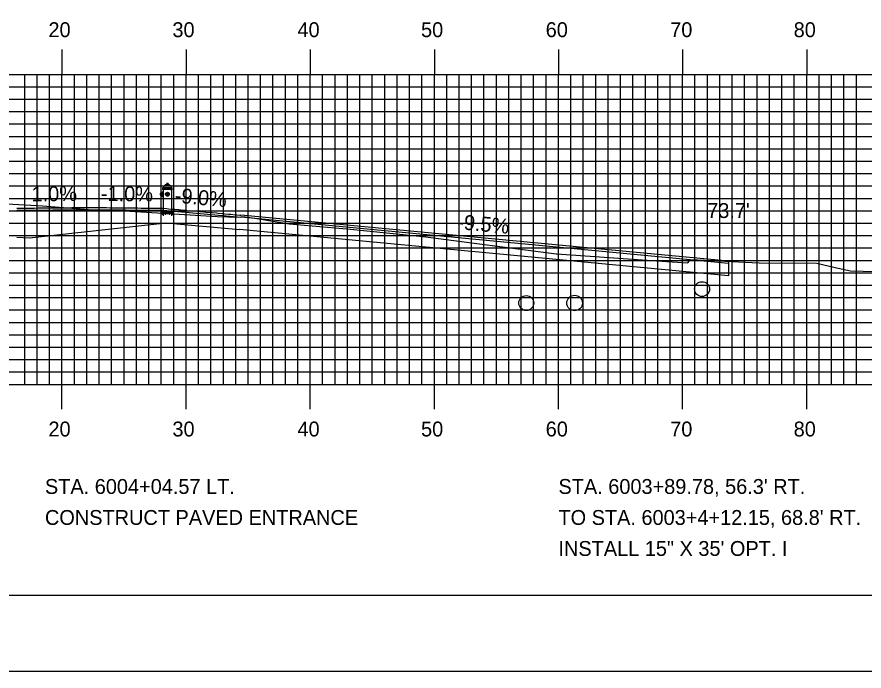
# Model space of a CAD drawing. Extents: x 852087 to 852430, y 366898 to 367118.
# Drawn here: x 852268.9 to 852337.2, y 366898.4 to 366951.1 of the extents above; entities that cross this region are included whole.
import ezdxf

# ---------------------------------------------------------------- set-up
doc = ezdxf.new("R2010")
doc.units = 0
for name, color, linetype in [('ANNOTATION', 7, 'Continuous'), ('BORDER', 7, 'Continuous'), ('D_Roadway_Centerline', 7, 'Continuous'), ('D_Roadway_Drive_Paved_RT', 7, 'Continuous'), ('D_Roadway_Drive_SubGrade', 7, 'Continuous'), ('D_Text_Standard', 7, 'Continuous'), ('H_V ANNOTATION', 7, 'Continuous'), ('MAJOR', 7, 'Continuous'), ('MINOR', 7, 'Continuous'), ('PLOT BOUNDARY', 7, 'Continuous'), ('S_Drainage_Invert', 7, 'Continuous'), ('S_Roadway_Centerline', 7, 'Continuous'), ('S_Utilities_Hydrant', 7, 'Continuous')]:
    doc.layers.add(name, color=color, linetype=linetype)

msp = doc.modelspace()

# ---------------------------------------------------------------- linework, layer by layer
at = {"layer": 'BORDER'}
msp.add_lwpolyline([(852102.931, 366904.473), (852422.931, 366904.473), (852422.931, 367114.473), (852102.931, 367114.473)], close=True, dxfattribs=at)
at = {"layer": 'D_Roadway_Centerline'}
msp.add_line((852326.234, 366931.398), (852286.944, 366935.114), dxfattribs=at)
msp.add_lwpolyline([(852268.9, 366935.68), (852269.116, 366935.682), (852269.261, 366935.684), (852269.616, 366935.687), (852269.771, 366935.689), (852270.117, 366935.692), (852270.28, 366935.694), (852270.617, 366935.697), (852270.79, 366935.699), (852271.117, 366935.702), (852271.299, 366935.704), (852271.617, 366935.707), (852271.808, 366935.709), (852272.118, 366935.712), (852272.317, 366935.714), (852272.618, 366935.717), (852272.826, 366935.719), (852273.118, 366935.722), (852273.334, 366935.724), (852273.618, 366935.727), (852273.843, 366935.73), (852274.119, 366935.732), (852274.352, 366935.735), (852274.619, 366935.737), (852274.645, 366935.738), (852274.675, 366935.738), (852274.889, 366935.736), (852275.119, 366935.733), (852275.368, 366935.731), (852275.619, 366935.728), (852275.876, 366935.726), (852276.119, 366935.723), (852276.384, 366935.721), (852276.62, 366935.718), (852276.892, 366935.716), (852277.12, 366935.713), (852277.4, 366935.711), (852277.62, 366935.708), (852277.907, 366935.706), (852278.12, 366935.703), (852278.413, 366935.7), (852278.621, 366935.698), (852278.92, 366935.695), (852279.121, 366935.693), (852279.426, 366935.69), (852279.621, 366935.688), (852279.931, 366935.685), (852280.121, 366935.683), (852280.436, 366935.68), (852280.622, 366935.678), (852280.657, 366935.678), (852280.677, 366935.678), (852280.961, 366935.652), (852281.122, 366935.638), (852281.444, 366935.609), (852281.622, 366935.593), (852281.948, 366935.564), (852282.122, 366935.548), (852282.451, 366935.518), (852282.622, 366935.503), (852282.955, 366935.473), (852283.123, 366935.458), (852283.458, 366935.428), (852283.623, 366935.413), (852283.962, 366935.382), (852284.123, 366935.368), (852284.466, 366935.337), (852284.623, 366935.323), (852284.969, 366935.292), (852285.124, 366935.278), (852285.473, 366935.246), (852285.624, 366935.233), (852285.977, 366935.201), (852286.124, 366935.188), (852286.481, 366935.156), (852286.624, 366935.143), (852286.854, 366935.122), (852286.944, 366935.114)], dxfattribs=at)
msp.add_circle((852313.831, 366928.029), 0.625, dxfattribs=at)
at = {"layer": 'D_Roadway_Drive_Paved_RT'}
msp.add_line((852326.234, 366931.231), (852286.929, 366934.948), dxfattribs=at)
msp.add_lwpolyline([(852268.902, 366935.513), (852274.675, 366935.571), (852280.669, 366935.511), (852286.929, 366934.948)], dxfattribs=at)
at = {"layer": 'D_Roadway_Drive_SubGrade'}
for p, q in [((852269.9, 366933.299), (852280.9, 366934.486)), ((852326.234, 366930.226), (852286.834, 366933.953)), ((852268.9, 366933.347), (852269.9, 366933.299)), ((852326.234, 366931.398), (852326.234, 366930.226))]:
    msp.add_line(p, q, dxfattribs=at)
msp.add_lwpolyline([(852280.9, 366934.486), (852286.84, 366933.952)], dxfattribs=at)
at = {"layer": 'MAJOR'}
for p, q in [((852272.531, 366948.477), (852272.531, 366946.473)), ((852282.531, 366948.477), (852282.531, 366946.473)), ((852292.531, 366948.477), (852292.531, 366946.473)), ((852302.531, 366948.477), (852302.531, 366946.473)), ((852312.531, 366948.477), (852312.531, 366946.473)), ((852322.531, 366948.477), (852322.531, 366946.473)), ((852332.531, 366948.477), (852332.531, 366946.473)), ((852112.531, 366946.473), (852392.531, 366946.473)), ((852112.531, 366946.473), (852392.531, 366946.473)), ((852272.531, 366921.473), (852272.531, 366946.473)), ((852282.531, 366921.473), (852282.531, 366946.473)), ((852292.531, 366921.473), (852292.531, 366946.473)), ((852302.531, 366921.473), (852302.531, 366946.473)), ((852312.531, 366921.473), (852312.531, 366946.473)), ((852322.531, 366921.473), (852322.531, 366946.473)), ((852332.531, 366921.473), (852332.531, 366946.473)), ((852112.531, 366941.473), (852392.531, 366941.473)), ((852112.531, 366936.473), (852392.531, 366936.473)), ((852112.531, 366931.473), (852392.531, 366931.473)), ((852112.531, 366926.473), (852392.531, 366926.473)), ((852112.531, 366921.473), (852392.531, 366921.473)), ((852112.531, 366921.473), (852392.531, 366921.473)), ((852272.531, 366919.469), (852272.531, 366921.473)), ((852282.531, 366919.469), (852282.531, 366921.473)), ((852292.531, 366919.469), (852292.531, 366921.473)), ((852302.531, 366919.469), (852302.531, 366921.473)), ((852312.531, 366919.469), (852312.531, 366921.473)), ((852322.531, 366919.469), (852322.531, 366921.473)), ((852332.531, 366919.469), (852332.531, 366921.473))]:
    msp.add_line(p, q, dxfattribs=at)
at = {"layer": 'MINOR'}
for p, q in [((852269.531, 366921.473), (852269.531, 366946.473)), ((852270.531, 366921.473), (852270.531, 366946.473)), ((852271.531, 366921.473), (852271.531, 366946.473)), ((852273.531, 366921.473), (852273.531, 366946.473)), ((852274.531, 366921.473), (852274.531, 366946.473)), ((852275.531, 366921.473), (852275.531, 366946.473)), ((852276.531, 366921.473), (852276.531, 366946.473)), ((852277.531, 366921.473), (852277.531, 366946.473)), ((852278.531, 366921.473), (852278.531, 366946.473)), ((852279.531, 366921.473), (852279.531, 366946.473)), ((852280.531, 366921.473), (852280.531, 366946.473)), ((852281.531, 366921.473), (852281.531, 366946.473)), ((852283.531, 366921.473), (852283.531, 366946.473)), ((852284.531, 366921.473), (852284.531, 366946.473)), ((852285.531, 366921.473), (852285.531, 366946.473)), ((852286.531, 366921.473), (852286.531, 366946.473)), ((852287.531, 366921.473), (852287.531, 366946.473)), ((852288.531, 366921.473), (852288.531, 366946.473)), ((852289.531, 366921.473), (852289.531, 366946.473)), ((852290.531, 366921.473), (852290.531, 366946.473)), ((852291.531, 366921.473), (852291.531, 366946.473)), ((852293.531, 366921.473), (852293.531, 366946.473)), ((852294.531, 366921.473), (852294.531, 366946.473)), ((852295.531, 366921.473), (852295.531, 366946.473)), ((852296.531, 366921.473), (852296.531, 366946.473)), ((852297.531, 366921.473), (852297.531, 366946.473)), ((852298.531, 366921.473), (852298.531, 366946.473)), ((852299.531, 366921.473), (852299.531, 366946.473)), ((852300.531, 366921.473), (852300.531, 366946.473)), ((852301.531, 366921.473), (852301.531, 366946.473)), ((852303.531, 366921.473), (852303.531, 366946.473)), ((852304.531, 366921.473), (852304.531, 366946.473)), ((852305.531, 366921.473), (852305.531, 366946.473)), ((852306.531, 366921.473), (852306.531, 366946.473)), ((852307.531, 366921.473), (852307.531, 366946.473)), ((852308.531, 366921.473), (852308.531, 366946.473)), ((852309.531, 366921.473), (852309.531, 366946.473)), ((852310.531, 366921.473), (852310.531, 366946.473)), ((852311.531, 366921.473), (852311.531, 366946.473)), ((852313.531, 366921.473), (852313.531, 366946.473)), ((852314.531, 366921.473), (852314.531, 366946.473)), ((852315.531, 366921.473), (852315.531, 366946.473)), ((852316.531, 366921.473), (852316.531, 366946.473)), ((852317.531, 366921.473), (852317.531, 366946.473)), ((852318.531, 366921.473), (852318.531, 366946.473)), ((852319.531, 366921.473), (852319.531, 366946.473)), ((852320.531, 366921.473), (852320.531, 366946.473)), ((852321.531, 366921.473), (852321.531, 366946.473)), ((852323.531, 366921.473), (852323.531, 366946.473)), ((852324.531, 366921.473), (852324.531, 366946.473)), ((852325.531, 366921.473), (852325.531, 366946.473)), ((852326.531, 366921.473), (852326.531, 366946.473)), ((852327.531, 366921.473), (852327.531, 366946.473)), ((852328.531, 366921.473), (852328.531, 366946.473)), ((852329.531, 366921.473), (852329.531, 366946.473)), ((852330.531, 366921.473), (852330.531, 366946.473)), ((852331.531, 366921.473), (852331.531, 366946.473)), ((852333.531, 366921.473), (852333.531, 366946.473)), ((852334.531, 366921.473), (852334.531, 366946.473)), ((852335.531, 366921.473), (852335.531, 366946.473)), ((852336.531, 366921.473), (852336.531, 366946.473)), ((852112.531, 366945.473), (852392.531, 366945.473)), ((852112.531, 366944.473), (852392.531, 366944.473)), ((852112.531, 366943.473), (852392.531, 366943.473)), ((852112.531, 366942.473), (852392.531, 366942.473)), ((852112.531, 366940.473), (852392.531, 366940.473)), ((852112.531, 366939.473), (852392.531, 366939.473)), ((852112.531, 366938.473), (852392.531, 366938.473)), ((852112.531, 366937.473), (852392.531, 366937.473)), ((852112.531, 366935.473), (852392.531, 366935.473)), ((852112.531, 366934.473), (852392.531, 366934.473)), ((852112.531, 366933.473), (852392.531, 366933.473)), ((852112.531, 366932.473), (852392.531, 366932.473)), ((852112.531, 366930.473), (852392.531, 366930.473)), ((852112.531, 366929.473), (852392.531, 366929.473)), ((852112.531, 366928.473), (852392.531, 366928.473)), ((852112.531, 366927.473), (852392.531, 366927.473)), ((852112.531, 366925.473), (852392.531, 366925.473)), ((852112.531, 366924.473), (852392.531, 366924.473)), ((852112.531, 366923.473), (852392.531, 366923.473)), ((852112.531, 366922.473), (852392.531, 366922.473))]:
    msp.add_line(p, q, dxfattribs=at)
at = {"layer": 'PLOT BOUNDARY'}
msp.add_lwpolyline([(852086.744, 366898.355), (852426.744, 366898.355), (852426.744, 367118.355), (852086.744, 367118.355)], close=True, dxfattribs=at)
at = {"layer": 'S_Drainage_Invert'}
for centre in [(852324.1, 366929.153), (852309.934, 366928.029)]:
    msp.add_circle(centre, 0.6, dxfattribs=at)
at = {"layer": 'S_Roadway_Centerline'}
msp.add_lwpolyline([(852265.692, 366936.178), (852270.959, 366935.859), (852275.688, 366935.504), (852277.536, 366935.463), (852280.218, 366935.302), (852285.045, 366935.019), (852286.748, 366934.969), (852287.106, 366935.015), (852288.227, 366934.848), (852290.827, 366934.417), (852295.786, 366933.99), (852296.825, 366933.883), (852301.329, 366933.423), (852301.551, 366933.405), (852301.618, 366933.399), (852312.348, 366932.011), (852312.406, 366931.999), (852320.438, 366931.424), (852322.942, 366931.276), (852323.159, 366931.547), (852328.693, 366931.279), (852333.354, 366931.242), (852334.838, 366930.897), (852336.074, 366930.619), (852341.222, 366930.486)], dxfattribs=at)
at = {"layer": 'S_Utilities_Hydrant'}
for p, q in [((852281.404, 366937.313), (852280.648, 366937.313)), ((852280.726, 366937.441), (852280.688, 366937.313)), ((852280.707, 366937.313), (852280.707, 366937.331)), ((852280.735, 366937.331), (852280.735, 366937.313)), ((852281.026, 366937.512), (852280.795, 366937.512)), ((852280.873, 366937.569), (852281.178, 366937.569)), ((852280.913, 366937.609), (852280.913, 366937.569)), ((852281.121, 366937.625), (852280.929, 366937.624)), ((852281.026, 366937.512), (852281.257, 366937.512)), ((852281.138, 366937.569), (852281.138, 366937.609)), ((852281.316, 366937.331), (852281.316, 366937.313)), ((852281.325, 366937.441), (852281.364, 366937.313)), ((852281.345, 366937.313), (852281.345, 366937.331)), ((852280.484, 366936.854), (852280.484, 366936.852)), ((852280.484, 366936.852), (852280.484, 366936.762)), ((852280.484, 366936.759), (852280.484, 366936.762)), ((852280.495, 366936.867), (852280.495, 366936.746)), ((852280.499, 366936.867), (852280.499, 366936.746)), ((852280.519, 366936.874), (852280.511, 366936.873)), ((852280.519, 366936.739), (852280.511, 366936.741)), ((852280.519, 366936.649), (852280.519, 366936.966)), ((852280.596, 366936.632), (852280.534, 366936.632)), ((852280.535, 366936.981), (852280.596, 366936.981)), ((852280.596, 366936.981), (852280.596, 366936.632)), ((852280.603, 366936.971), (852280.596, 366936.971)), ((852280.603, 366936.643), (852280.596, 366936.643)), ((852280.603, 366936.638), (852280.603, 366936.976)), ((852280.631, 366937.298), (852280.631, 366937.216)), ((852281.42, 366937.257), (852280.631, 366937.257)), ((852280.688, 366937.201), (852280.688, 366935.394)), ((852280.688, 366937.042), (852280.688, 366937.042)), ((852280.707, 366937.176), (852280.707, 366937.201)), ((852280.735, 366937.201), (852280.735, 366937.176)), ((852281.316, 366937.201), (852281.316, 366937.176)), ((852281.345, 366937.176), (852281.345, 366937.201)), ((852281.364, 366937.201), (852281.364, 366935.394)), ((852280.688, 366936.571), (852280.688, 366936.571)), ((852281.507, 366935.338), (852280.555, 366935.338)), ((852281.507, 366935.281), (852280.555, 366935.281)), ((852280.581, 366935.394), (852281.482, 366935.394)), ((852280.616, 366935.411), (852280.616, 366935.394)), ((852280.643, 366935.394), (852280.643, 366935.411)), ((852280.867, 366935.411), (852280.867, 366935.394)), ((852280.895, 366935.394), (852280.895, 366935.411)), ((852281.167, 366935.411), (852281.167, 366935.394)), ((852281.195, 366935.394), (852281.195, 366935.411)), ((852281.419, 366935.411), (852281.419, 366935.394)), ((852281.447, 366935.394), (852281.447, 366935.411)), ((852281.482, 366935.225), (852280.581, 366935.225)), ((852280.616, 366935.225), (852280.616, 366935.201)), ((852280.643, 366935.201), (852280.643, 366935.225)), ((852280.688, 366935.225), (852280.688, 366935.058)), ((852280.867, 366935.225), (852280.867, 366935.201)), ((852280.895, 366935.201), (852280.895, 366935.225)), ((852281.167, 366935.225), (852281.167, 366935.201)), ((852281.195, 366935.201), (852281.195, 366935.225)), ((852281.364, 366935.225), (852281.364, 366935.058)), ((852281.419, 366935.225), (852281.419, 366935.201)), ((852281.447, 366935.201), (852281.447, 366935.225))]:
    msp.add_line(p, q, dxfattribs=at)
for points in [[(852280.693, 366937.313), (852280.693, 366937.331), (852280.696, 366937.334), (852280.745, 366937.334), (852280.749, 366937.331), (852280.749, 366937.313), (852280.693, 366937.313)], [(852280.856, 366937.512), (852280.856, 366937.554), (852280.857, 366937.554), (852280.856, 366937.554)], [(852281.082, 366937.624), (852281.082, 366937.681), (852280.969, 366937.681), (852280.969, 366937.624)], [(852281.194, 366937.554), (852281.194, 366937.554), (852281.194, 366937.554), (852281.194, 366937.512)], [(852281.358, 366937.313), (852281.358, 366937.331), (852281.354, 366937.334), (852281.306, 366937.334), (852281.302, 366937.331), (852281.302, 366937.313), (852281.358, 366937.313)], [(852280.484, 366936.852), (852280.449, 366936.852), (852280.449, 366936.762), (852280.484, 366936.762)], [(852280.646, 366937.2), (852280.646, 366937.201), (852281.404, 366937.201), (852281.404, 366937.2)], [(852280.749, 366937.201), (852280.749, 366937.176), (852280.745, 366937.172), (852280.696, 366937.172), (852280.693, 366937.176), (852280.693, 366937.201), (852280.749, 366937.201)], [(852280.707, 366937.18), (852280.707, 366937.163), (852280.735, 366937.163), (852280.735, 366937.176)], [(852281.058, 366936.762), (852280.993, 366936.762), (852280.974, 366936.823), (852281.026, 366936.861), (852281.077, 366936.823), (852281.058, 366936.762)], [(852281.302, 366937.201), (852281.302, 366937.176), (852281.306, 366937.172), (852281.354, 366937.172), (852281.358, 366937.176), (852281.358, 366937.201), (852281.302, 366937.201)], [(852281.345, 366937.18), (852281.345, 366937.163), (852281.316, 366937.163), (852281.316, 366937.176)], [(852281.42, 366937.216), (852281.42, 366937.297), (852281.42, 366937.298)], [(852280.658, 366935.394), (852280.658, 366935.411), (852280.654, 366935.415), (852280.605, 366935.415), (852280.601, 366935.411), (852280.601, 366935.394), (852280.658, 366935.394)], [(852280.909, 366935.394), (852280.909, 366935.411), (852280.905, 366935.415), (852280.856, 366935.415), (852280.852, 366935.411), (852280.852, 366935.394), (852280.909, 366935.394)], [(852281.209, 366935.394), (852281.209, 366935.411), (852281.205, 366935.415), (852281.157, 366935.415), (852281.153, 366935.411), (852281.153, 366935.394), (852281.209, 366935.394)], [(852281.461, 366935.394), (852281.461, 366935.411), (852281.457, 366935.415), (852281.408, 366935.415), (852281.404, 366935.411), (852281.404, 366935.394), (852281.461, 366935.394)], [(852280.601, 366935.225), (852280.601, 366935.201), (852280.605, 366935.197), (852280.654, 366935.197), (852280.658, 366935.201), (852280.658, 366935.225), (852280.601, 366935.225)], [(852280.643, 366935.204), (852280.643, 366935.187), (852280.616, 366935.187), (852280.616, 366935.201)], [(852280.852, 366935.225), (852280.852, 366935.201), (852280.856, 366935.197), (852280.905, 366935.197), (852280.909, 366935.201), (852280.909, 366935.225), (852280.852, 366935.225)], [(852280.895, 366935.204), (852280.895, 366935.187), (852280.867, 366935.187), (852280.867, 366935.201)], [(852281.153, 366935.225), (852281.153, 366935.201), (852281.157, 366935.197), (852281.205, 366935.197), (852281.209, 366935.201), (852281.209, 366935.225), (852281.153, 366935.225)], [(852281.195, 366935.204), (852281.195, 366935.187), (852281.167, 366935.187), (852281.167, 366935.201)], [(852281.404, 366935.225), (852281.404, 366935.201), (852281.408, 366935.197), (852281.457, 366935.197), (852281.461, 366935.201), (852281.461, 366935.225), (852281.404, 366935.225)], [(852281.447, 366935.204), (852281.447, 366935.187), (852281.419, 366935.187), (852281.419, 366935.201)]]:
    msp.add_lwpolyline(points, dxfattribs=at)
for radius in [0.158, 0.128]:
    msp.add_circle((852281.026, 366936.806), radius, dxfattribs=at)
for centre, radius, start, end in [((852280.65, 366937.294), 0.0191, 96.99212, 168.80283), ((852280.7, 366937.326), 0.00826, 32.91438, 129.49387), ((852280.721, 366937.306), 0.0282, 60.00073, 120.00073), ((852280.818, 366937.421), 0.0943, 104.42432, 167.48007), ((852280.742, 366937.326), 0.00826, 50.50638, 147.08587), ((852280.875, 366937.55), 0.0191, 96.99212, 168.80284), ((852280.932, 366937.606), 0.019, 96.60086, 168.41157), ((852281.119, 366937.606), 0.0191, 11.19716, 83.00788), ((852281.176, 366937.55), 0.019, 11.5319, 83.34262), ((852281.233, 366937.421), 0.0943, 12.51993, 75.57568), ((852281.309, 366937.326), 0.00826, 32.91413, 129.49362), ((852281.33, 366937.306), 0.0282, 59.99927, 119.99927), ((852281.351, 366937.326), 0.00826, 50.50613, 147.08562), ((852281.401, 366937.294), 0.0191, 11.19716, 83.00788), ((852280.562, 366936.851), 0.0782, 170.53768, 171.43407), ((852280.493, 366936.862), 0.00865, 171.43408, 174.12815), ((852280.497, 366936.861), 0.013, 174.12815, 177.71824), ((852280.613, 366936.857), 0.128, 177.71824, 178.85931), ((852280.57, 366936.857), 0.0857, 178.85931, 179.71502), ((852281.257, 366936.854), 0.772, 179.71503, 180), ((852281.257, 366936.759), 0.772, 180, 180.28497), ((852280.57, 366936.755), 0.0857, 180.28497, 181.14069), ((852280.613, 366936.756), 0.128, 181.14069, 182.28176), ((852280.497, 366936.752), 0.013, 182.28176, 185.87185), ((852280.562, 366936.762), 0.0782, 188.56593, 189.46232), ((852280.493, 366936.751), 0.00865, 185.87185, 188.56592), ((852280.494, 366936.86), 0.0104, 141.34019, 150.64225), ((852280.487, 366936.864), 0.00229, 150.64225, 170.53768), ((852280.487, 366936.749), 0.00229, 189.46232, 209.35775), ((852280.494, 366936.753), 0.0104, 209.35775, 218.65981), ((852280.443, 366936.901), 0.055, 321.34019, 323.1301), ((852280.443, 366936.712), 0.055, 36.8699, 38.65981), ((852280.488, 366936.868), 0.000947, 97.12502, 146.30993), ((852280.473, 366936.878), 0.0174, 323.1301, 326.30993), ((852280.473, 366936.735), 0.0174, 33.69007, 36.8699), ((852280.488, 366936.745), 0.000947, 213.69007, 262.87498), ((852280.488, 366936.866), 0.00335, 71.56505, 97.12501), ((852280.488, 366936.747), 0.00335, 262.87499, 288.43495), ((852280.48, 366936.841), 0.0288, 68.19859, 71.56505), ((852280.48, 366936.772), 0.0288, 288.43495, 291.80141), ((852280.486, 366936.855), 0.0144, 63.43495, 68.19859), ((852280.486, 366936.758), 0.0144, 291.80141, 296.56505), ((852280.496, 366936.875), 0.0084, 243.43495, 251.56505), ((852280.496, 366936.738), 0.0084, 108.43495, 116.56505), ((852280.497, 366936.878), 0.0109, 251.56505, 258.69007), ((852280.497, 366936.735), 0.0109, 101.30993, 108.43495), ((852280.496, 366936.874), 0.00686, 258.69007, 270), ((852280.496, 366936.739), 0.00686, 90, 101.30993), ((852280.496, 366936.884), 0.0173, 270, 277.12502), ((852280.496, 366936.729), 0.0173, 82.87498, 90), ((852280.497, 366936.874), 0.00682, 277.12502, 294.44396), ((852280.497, 366936.739), 0.00682, 65.55604, 82.87498), ((852280.499, 366936.87), 0.00252, 294.44396, 323.1301), ((852280.499, 366936.743), 0.00252, 36.8699, 65.55604), ((852280.509, 366936.863), 0.00939, 135, 143.1301), ((852280.509, 366936.75), 0.00939, 216.8699, 225), ((852280.509, 366936.863), 0.00939, 126.8699, 135), ((852280.509, 366936.75), 0.00939, 225, 233.1301), ((852280.505, 366936.867), 0.00357, 105.73724, 126.8699), ((852280.505, 366936.746), 0.00357, 233.1301, 254.26276), ((852280.536, 366936.758), 0.117, 102.06194, 105.73724), ((852280.536, 366936.855), 0.117, 254.26276, 257.93806), ((852280.538, 366936.962), 0.0191, 96.99212, 168.80284), ((852280.538, 366936.651), 0.0192, 186.73277, 258.54349), ((852280.59, 366937.079), 0.105, 277.42338, 339.52992), ((852280.59, 366936.534), 0.105, 20.47008, 82.57662), ((852280.65, 366937.219), 0.0191, 186.99212, 258.80283), ((852280.7, 366937.181), 0.00826, 230.50638, 327.08587), ((852280.721, 366937.201), 0.0282, 240.00073, 300.00073), ((852280.742, 366937.181), 0.00826, 212.91438, 309.49387), ((852281.309, 366937.181), 0.00826, 230.50613, 327.08562), ((852281.33, 366937.201), 0.0282, 239.99927, 299.99927), ((852281.351, 366937.181), 0.00826, 212.91413, 309.49362), ((852281.401, 366937.219), 0.0191, 281.19716, 353.00788), ((852280.693, 366935.31), 0.141, 143.1301, 216.8699), ((852280.608, 366935.407), 0.00826, 32.91413, 129.49362), ((852280.629, 366935.387), 0.0282, 59.99927, 119.99927), ((852280.65, 366935.407), 0.00826, 50.50613, 147.08562), ((852280.86, 366935.407), 0.00826, 32.91413, 129.49362), ((852280.881, 366935.387), 0.0282, 59.99927, 119.99927), ((852280.902, 366935.407), 0.00826, 50.50613, 147.08562), ((852281.16, 366935.407), 0.00826, 32.91413, 129.49362), ((852281.181, 366935.387), 0.0282, 59.99927, 119.99927), ((852281.202, 366935.407), 0.00826, 50.50613, 147.08562), ((852281.412, 366935.407), 0.00826, 32.91413, 129.49362), ((852281.433, 366935.387), 0.0282, 59.99927, 119.99927), ((852281.454, 366935.407), 0.00826, 50.50613, 147.08562), ((852281.369, 366935.31), 0.141, 323.1301, 36.8699), ((852280.608, 366935.205), 0.00826, 230.50613, 327.08562), ((852280.629, 366935.225), 0.0282, 239.99927, 299.99927), ((852280.65, 366935.205), 0.00826, 212.91413, 309.49362), ((852280.86, 366935.205), 0.00826, 230.50613, 327.08562), ((852280.881, 366935.225), 0.0282, 239.99927, 299.99927), ((852280.902, 366935.205), 0.00826, 212.91413, 309.49362), ((852281.16, 366935.205), 0.00826, 230.50613, 327.08562), ((852281.181, 366935.225), 0.0282, 239.99927, 299.99927), ((852281.202, 366935.205), 0.00826, 212.91413, 309.49362), ((852281.412, 366935.205), 0.00826, 230.50613, 327.08562), ((852281.433, 366935.225), 0.0282, 239.99927, 299.99927), ((852281.454, 366935.205), 0.00826, 212.91413, 309.49362)]:
    msp.add_arc(centre, radius, start, end, dxfattribs=at)

# ---------------------------------------------------------------- texts
at = {"layer": 'ANNOTATION'}
for s, rotation, p in [('1.0%', 0.57267, (852270.084, 366936.226)), ('-1.0%', 359.43015, (852275.662, 366936.262)), ('-9.0%', 354.85961, (852281.578, 366936.133)), ('-9.5%', 354.5973, (852304.338, 366934.005))]:
    msp.add_text(s, height=1.2, rotation=rotation, dxfattribs=at).set_placement(p)
at = {"layer": 'D_Text_Standard'}
for s, p in [("73.7'", (852324.515, 366934.89)), ('STA. 6004+04.57 LT.', (852271.157, 366912.64)), ("STA. 6003+89.78, 56.3' RT.", (852312.531, 366912.64)), ('CONSTRUCT PAVED ENTRANCE', (852271.157, 366910.14)), ("TO STA. 6003+4+12.15, 68.8' RT.", (852312.531, 366910.14)), ('INSTALL 15" X 35\' OPT. I', (852312.531, 366907.64))]:
    msp.add_text(s, height=1.2, dxfattribs=at).set_placement(p)
at = {"layer": 'H_V ANNOTATION'}
for s, p in [('20', (852271.439, 366949.473)), ('30', (852281.428, 366949.473)), ('40', (852291.503, 366949.473)), ('50', (852301.46, 366949.473)), ('60', (852311.503, 366949.473)), ('70', (852321.535, 366949.473)), ('80', (852331.482, 366949.473)), ('20', (852271.439, 366917.273)), ('30', (852281.428, 366917.273)), ('40', (852291.503, 366917.273)), ('50', (852301.46, 366917.273)), ('60', (852311.503, 366917.273)), ('70', (852321.535, 366917.273)), ('80', (852331.482, 366917.273))]:
    msp.add_text(s, height=1.2, dxfattribs=at).set_placement(p)

doc.saveas('drawing.dxf')
